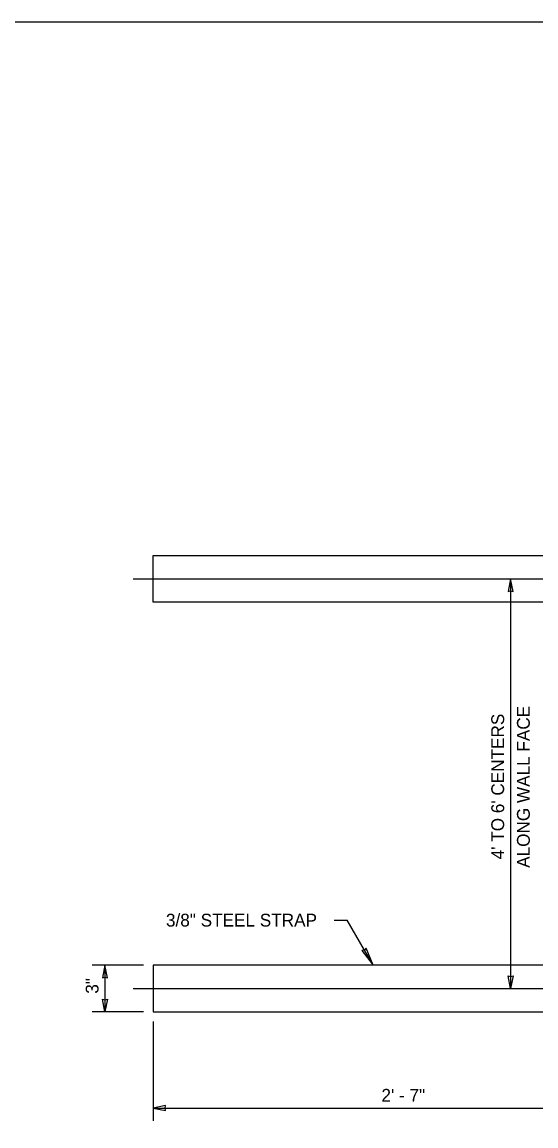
# Model space of a CAD drawing. Extents: x 99862 to 103151, y 100000 to 111076.
# Drawn here: x 101506 to 102147, y 109698 to 111076 of the extents above; entities that cross this region are included whole.
import ezdxf

# ---------------------------------------------------------------- set-up
doc = ezdxf.new("R2010")
doc.units = 0
for name, color, linetype in [('Level 1', 7, 'Continuous'), ('Level 15', 7, 'Continuous'), ('Level 20', 7, 'Continuous'), ('Level 24', 7, 'Continuous')]:
    doc.layers.add(name, color=color, linetype=linetype)

msp = doc.modelspace()

# ---------------------------------------------------------------- linework, layer by layer
at = {"layer": 'Level 1'}
msp.add_lwpolyline([(99862, 108999.5), (103151, 108999.5), (103151, 111075.5), (99862, 111075.5)], close=True, dxfattribs=at)
at = {"layer": 'Level 15'}
for p, q in [((101644.8, 110380.6), (102329.4, 110380.6)), ((102115.6, 110380.6), (102115.6, 109869.2)), ((101895.7, 109954.6), (101911.7, 109954.6)), ((101944.2, 109898.3), (101911.7, 109954.6)), ((101657.8, 109898.3), (101593.8, 109898.3)), ((101609.8, 109898.3), (101609.8, 109840)), ((101644.8, 109869.2), (102329.4, 109869.2)), ((101657.8, 109840), (101593.8, 109840)), ((101669.8, 109828), (101669.8, 109704)), ((101669.8, 109720), (102290.1, 109720))]:
    msp.add_line(p, q, dxfattribs=at)
for points in [[(102115.6, 110380.6), (102112.5, 110364.9), (102115.6, 110365.7), (102118.7, 110364.9)], [(101944.2, 109898.3), (101935.4, 109919.5), (101933.4, 109917.1), (101930.2, 109916.6)], [(101609.8, 109898.3), (101606.7, 109882.6), (101609.8, 109883.3), (101612.9, 109882.6)], [(102115.6, 109869.2), (102112.5, 109885), (102115.6, 109884.2), (102118.7, 109885)], [(101609.8, 109840), (101606.7, 109855.8), (101609.8, 109855), (101612.9, 109855.8)], [(101669.8, 109720), (101685.5, 109716.9), (101684.8, 109720), (101685.5, 109723.1)]]:
    msp.add_lwpolyline(points, close=True, dxfattribs=at)
at = {"layer": 'Level 24'}
for points in [[(102218.7, 110351.5), (101669.8, 110351.5), (101669.8, 110409.8), (102218.7, 110409.8)], [(102218.7, 109898.3), (101669.8, 109898.3), (101669.8, 109840), (102218.7, 109840)]]:
    msp.add_lwpolyline(points, dxfattribs=at)

# ---------------------------------------------------------------- texts
at = {"layer": 'Level 20'}
for s, p in [('ALONG WALL FACE', (102139.6, 110019.9)), ("4' TO 6' CENTERS", (102107.6, 110030.5)), ('3"', (101601.8, 109862.8))]:
    msp.add_text(s, height=16, rotation=90, dxfattribs=at).set_placement(p)
for s, p in [('3/8" STEEL STRAP', (101685.9, 109946.6)), ('2\' - 7"', (101954.6, 109728))]:
    msp.add_text(s, height=16, dxfattribs=at).set_placement(p)

doc.saveas('drawing.dxf')
